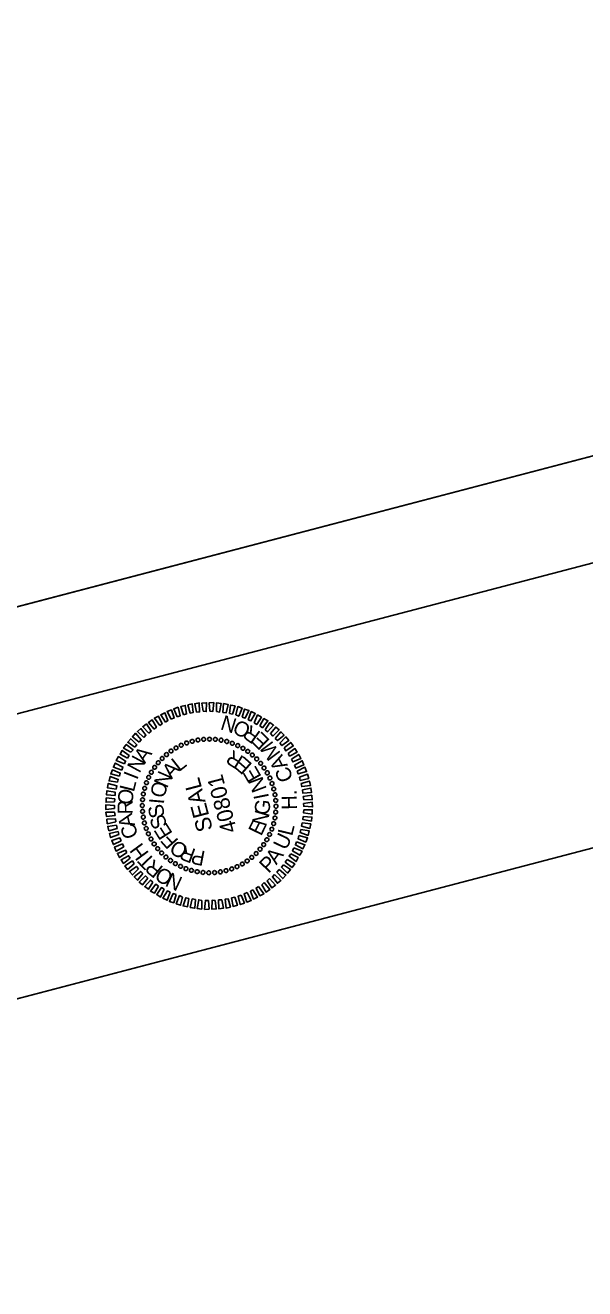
# Model space of a CAD drawing. Extents: x 1366711 to 1368206, y 878140 to 880064.
# Drawn here: x 1366973.2 to 1367176, y 879605.6 to 880063.8 of the extents above; entities that cross this region are included whole.
import ezdxf

# ---------------------------------------------------------------- set-up
doc = ezdxf.new("R2010")
doc.units = 0
for name, color, linetype in [('Exist Hydro Jurisdictional Stream or Body of Water Mitigable Cogo Number', 7, 'Continuous'), ('Exist Hydro Jurisdictional Stream or Body of Water NonMitigable', 7, 'Continuous'), ('Sheet_Data_Field_CELL', 7, 'Continuous'), ('Sheet_Data_Text_CELL', 7, 'Continuous'), ('Sheet_Plan_CELL', 7, 'Continuous')]:
    doc.layers.add(name, color=color, linetype=linetype)

msp = doc.modelspace()

# ---------------------------------------------------------------- linework, layer by layer
at = {"layer": 'Exist Hydro Jurisdictional Stream or Body of Water Mitigable Cogo Number'}
for p, q in [((1367748.14, 880017.97), (1366756.62, 879758.15)), ((1367773.49, 879921.24), (1366781.97, 879661.42))]:
    msp.add_line(p, q, dxfattribs=at)
at = {"layer": 'Exist Hydro Jurisdictional Stream or Body of Water NonMitigable'}
msp.add_line((1367774.9, 880063.78), (1366710.84, 879784.92), dxfattribs=at)
at = {"layer": 'Sheet_Data_Field_CELL'}
for p, q in [((1367037.9, 879804.8), (1367037.9, 879804.8)), ((1367039.98, 879804.93), (1367039.98, 879804.93)), ((1367042.11, 879804.82), (1367042.11, 879804.82)), ((1367026.03, 879800.61), (1367026.03, 879800.61)), ((1367027.83, 879801.72), (1367027.83, 879801.72)), ((1367029.77, 879802.66), (1367029.77, 879802.66)), ((1367031.69, 879803.5), (1367031.69, 879803.5)), ((1367033.73, 879804.12), (1367033.73, 879804.12)), ((1367035.81, 879804.56), (1367035.81, 879804.56)), ((1367044.21, 879804.51), (1367044.21, 879804.51)), ((1367046.28, 879804.09), (1367046.28, 879804.09)), ((1367048.29, 879803.39), (1367048.29, 879803.39)), ((1367050.27, 879802.6), (1367050.27, 879802.6)), ((1367052.1, 879801.61), (1367052.1, 879801.61)), ((1367053.93, 879800.46), (1367053.93, 879800.46)), ((1367021.36, 879796.34), (1367021.36, 879796.34)), ((1367022.83, 879797.9), (1367022.83, 879797.9)), ((1367024.38, 879799.34), (1367024.38, 879799.34)), ((1367055.55, 879799.16), (1367055.55, 879799.16)), ((1367057.11, 879797.69), (1367057.11, 879797.69)), ((1367058.55, 879796.14), (1367058.55, 879796.14)), ((1367017.92, 879791.06), (1367017.92, 879791.06)), ((1367018.91, 879792.89), (1367018.91, 879792.89)), ((1367020.06, 879794.71), (1367020.06, 879794.71)), ((1367059.82, 879794.49), (1367059.82, 879794.49)), ((1367060.93, 879792.69), (1367060.93, 879792.69)), ((1367016.43, 879787.07), (1367016.43, 879787.07)), ((1367017.13, 879789.08), (1367017.13, 879789.08)), ((1367061.87, 879790.75), (1367061.87, 879790.75)), ((1367062.71, 879788.83), (1367062.71, 879788.83)), ((1367063.33, 879786.8), (1367063.33, 879786.8)), ((1367015.7, 879782.9), (1367015.7, 879782.9)), ((1367016.01, 879785), (1367016.01, 879785)), ((1367063.77, 879784.71), (1367063.77, 879784.71)), ((1367064.01, 879782.62), (1367064.01, 879782.62)), ((1367015.59, 879780.77), (1367015.59, 879780.77)), ((1367015.72, 879778.69), (1367015.72, 879778.69)), ((1367039.86, 879780.66), (1367039.86, 879780.66)), ((1367064.03, 879778.41), (1367064.03, 879778.41)), ((1367064.14, 879780.55), (1367064.14, 879780.55)), ((1367015.96, 879776.6), (1367015.96, 879776.6)), ((1367016.4, 879774.52), (1367016.4, 879774.52)), ((1367063.3, 879774.24), (1367063.3, 879774.24)), ((1367063.72, 879776.31), (1367063.72, 879776.31)), ((1367017.02, 879772.48), (1367017.02, 879772.48)), ((1367017.86, 879770.56), (1367017.86, 879770.56)), ((1367018.8, 879768.62), (1367018.8, 879768.62)), ((1367060.82, 879768.42), (1367060.82, 879768.42)), ((1367061.81, 879770.26), (1367061.81, 879770.26)), ((1367062.6, 879772.24), (1367062.6, 879772.24)), ((1367019.91, 879766.82), (1367019.91, 879766.82)), ((1367021.18, 879765.17), (1367021.18, 879765.17)), ((1367022.62, 879763.62), (1367022.62, 879763.62)), ((1367058.37, 879764.98), (1367058.37, 879764.98)), ((1367059.67, 879766.59), (1367059.67, 879766.59)), ((1367024.18, 879762.15), (1367024.18, 879762.15)), ((1367025.8, 879760.85), (1367025.8, 879760.85)), ((1367027.63, 879759.7), (1367027.63, 879759.7)), ((1367051.9, 879759.6), (1367051.9, 879759.6)), ((1367053.7, 879760.7), (1367053.7, 879760.7)), ((1367055.35, 879761.97), (1367055.35, 879761.97)), ((1367056.9, 879763.41), (1367056.9, 879763.41)), ((1367029.46, 879758.71), (1367029.46, 879758.71)), ((1367031.45, 879757.92), (1367031.45, 879757.92)), ((1367033.45, 879757.22), (1367033.45, 879757.22)), ((1367035.52, 879756.8), (1367035.52, 879756.8)), ((1367037.62, 879756.49), (1367037.62, 879756.49)), ((1367039.76, 879756.38), (1367039.76, 879756.38)), ((1367041.83, 879756.51), (1367041.83, 879756.51)), ((1367043.92, 879756.75), (1367043.92, 879756.75)), ((1367046.01, 879757.19), (1367046.01, 879757.19)), ((1367048.04, 879757.81), (1367048.04, 879757.81)), ((1367049.96, 879758.65), (1367049.96, 879758.65))]:
    msp.add_line(p, q, dxfattribs=at)
for points in [[(1367024.01, 879811.03), (1367022.3, 879813.71), (1367023.81, 879814.44), (1367024.91, 879811.59)], [(1367026.13, 879812.08), (1367024.62, 879814.92), (1367026.16, 879815.5), (1367027.19, 879812.58)], [(1367028.28, 879812.98), (1367027.06, 879815.9), (1367028.61, 879816.44), (1367029.37, 879813.39)], [(1367030.59, 879813.68), (1367029.6, 879816.67), (1367031.18, 879817.11), (1367031.71, 879814)], [(1367032.93, 879814.29), (1367032.17, 879817.34), (1367033.74, 879817.68), (1367034.07, 879814.51)], [(1367035.23, 879814.68), (1367034.67, 879817.74), (1367036.3, 879818), (1367036.41, 879814.77)], [(1367037.71, 879814.98), (1367037.27, 879817.97), (1367038.94, 879818.09), (1367038.79, 879814.88)], [(1367040.11, 879815), (1367039.9, 879818.05), (1367041.53, 879818.16), (1367041.19, 879814.9)], [(1367042.54, 879814.93), (1367042.56, 879818.05), (1367044.18, 879817.85), (1367043.66, 879814.69)], [(1367044.85, 879814.57), (1367045.11, 879817.76), (1367046.74, 879817.47), (1367046, 879814.4)], [(1367047.24, 879814.24), (1367047.67, 879817.22), (1367049.3, 879816.93), (1367048.29, 879813.94)], [(1367049.56, 879813.69), (1367050.22, 879816.69), (1367051.79, 879816.12), (1367050.61, 879813.18)], [(1367051.81, 879812.82), (1367052.69, 879815.77), (1367054.29, 879815.27), (1367052.87, 879812.46)], [(1367053.97, 879811.92), (1367055.11, 879814.85), (1367056.6, 879814.16), (1367054.99, 879811.5)], [(1367017.96, 879807.02), (1367015.79, 879809.38), (1367017.11, 879810.4), (1367018.85, 879807.78)], [(1367019.91, 879808.48), (1367017.9, 879810.97), (1367019.2, 879811.89), (1367020.75, 879809.21)], [(1367021.93, 879809.85), (1367020.02, 879812.52), (1367021.48, 879813.23), (1367022.82, 879810.45)], [(1367056.2, 879810.79), (1367057.44, 879813.69), (1367058.83, 879812.83), (1367057.15, 879810.25)], [(1367058.26, 879809.71), (1367059.73, 879812.33), (1367061.16, 879811.53), (1367059.16, 879809.01)], [(1367060.22, 879808.25), (1367061.89, 879810.88), (1367063.22, 879809.9), (1367061.07, 879807.54)], [(1367012.94, 879802), (1367010.35, 879803.73), (1367011.45, 879805), (1367013.67, 879802.81)], [(1367014.51, 879803.75), (1367012.05, 879805.72), (1367013.2, 879806.99), (1367015.26, 879804.66)], [(1367016.22, 879805.53), (1367013.86, 879807.68), (1367015.13, 879808.69), (1367016.94, 879806.34)], [(1367062.11, 879806.88), (1367064, 879809.26), (1367065.22, 879808.3), (1367062.96, 879806.01)], [(1367063.85, 879805.16), (1367065.88, 879807.58), (1367067.03, 879806.35), (1367064.66, 879804.43)], [(1367065.53, 879803.47), (1367067.72, 879805.69), (1367068.77, 879804.43), (1367066.23, 879802.56)], [(1367010.3, 879798), (1367007.55, 879799.38), (1367008.36, 879800.81), (1367010.85, 879798.91)], [(1367011.52, 879800.1), (1367008.83, 879801.65), (1367009.81, 879802.98), (1367012.27, 879801.01)], [(1367067.08, 879801.7), (1367069.44, 879803.67), (1367070.39, 879802.43), (1367067.69, 879800.61)], [(1367068.46, 879799.63), (1367070.95, 879801.48), (1367071.78, 879800.16), (1367069.06, 879798.74)], [(1367008.2, 879793.69), (1367005.16, 879794.7), (1367005.84, 879796.19), (1367008.6, 879794.76)], [(1367009.14, 879795.87), (1367006.19, 879797.1), (1367006.99, 879798.53), (1367009.6, 879796.95)], [(1367069.7, 879797.57), (1367072.35, 879799.36), (1367073.12, 879797.87), (1367070.2, 879796.65)], [(1367070.83, 879795.48), (1367073.6, 879797.06), (1367074.17, 879795.56), (1367071.29, 879794.4)], [(1367006.59, 879789.23), (1367003.59, 879789.74), (1367003.99, 879791.36), (1367006.9, 879790.27)], [(1367007.34, 879791.4), (1367004.18, 879792.26), (1367004.82, 879793.75), (1367007.61, 879792.58)], [(1367071.74, 879793.32), (1367074.57, 879794.67), (1367075.2, 879793.14), (1367072.19, 879792.25)], [(1367072.63, 879791.06), (1367075.58, 879792.14), (1367075.97, 879790.59), (1367072.89, 879789.93)], [(1367006.12, 879786.79), (1367003.05, 879787.18), (1367003.3, 879788.81), (1367006.35, 879787.96)], [(1367073.21, 879788.81), (1367076.23, 879789.66), (1367076.62, 879788.12), (1367073.47, 879787.69)], [(1367073.72, 879786.45), (1367076.79, 879787.11), (1367076.95, 879785.5), (1367073.85, 879785.28)], [(1367005.58, 879782.12), (1367002.5, 879782.01), (1367002.56, 879783.58), (1367005.63, 879783.19)], [(1367005.83, 879784.45), (1367002.6, 879784.69), (1367002.79, 879786.16), (1367005.85, 879785.61)], [(1367073.97, 879784.11), (1367077.07, 879784.53), (1367077.27, 879782.93), (1367074.15, 879782.95)], [(1367074.13, 879781.59), (1367077.28, 879781.98), (1367077.36, 879780.29), (1367074.17, 879780.55)], [(1367005.6, 879779.72), (1367002.45, 879779.33), (1367002.38, 879781.02), (1367005.56, 879780.76)], [(1367005.75, 879777.2), (1367002.66, 879776.78), (1367002.46, 879778.38), (1367005.58, 879778.36)], [(1367074.15, 879779.19), (1367077.23, 879779.3), (1367077.17, 879777.73), (1367074.1, 879778.12)], [(1367006.01, 879774.86), (1367002.93, 879774.2), (1367002.78, 879775.81), (1367005.88, 879776.03)], [(1367006.52, 879772.5), (1367003.5, 879771.65), (1367003.12, 879773.2), (1367006.26, 879773.63)], [(1367073.61, 879774.52), (1367076.68, 879774.13), (1367076.43, 879772.51), (1367073.38, 879773.36)], [(1367073.9, 879776.86), (1367077.13, 879776.62), (1367076.94, 879775.16), (1367073.88, 879775.7)], [(1367007.1, 879770.25), (1367004.15, 879769.17), (1367003.76, 879770.72), (1367006.84, 879771.38)], [(1367007.99, 879767.99), (1367005.16, 879766.64), (1367004.53, 879768.17), (1367007.54, 879769.07)], [(1367072.39, 879769.92), (1367075.55, 879769.04), (1367074.91, 879767.56), (1367072.12, 879768.74)], [(1367073.14, 879772.08), (1367076.14, 879771.57), (1367075.74, 879769.95), (1367072.83, 879771.04)], [(1367008.9, 879765.84), (1367006.13, 879764.26), (1367005.56, 879765.75), (1367008.44, 879766.91)], [(1367010.04, 879763.75), (1367007.38, 879761.95), (1367006.61, 879763.44), (1367009.53, 879764.66)], [(1367070.59, 879765.44), (1367073.54, 879764.22), (1367072.74, 879762.79), (1367070.14, 879764.36)], [(1367071.53, 879767.62), (1367074.57, 879766.61), (1367073.89, 879765.12), (1367071.13, 879766.55)], [(1367011.27, 879761.68), (1367008.78, 879759.83), (1367007.95, 879761.15), (1367010.67, 879762.57)], [(1367012.65, 879759.61), (1367010.29, 879757.65), (1367009.34, 879758.89), (1367012.05, 879760.7)], [(1367066.79, 879759.31), (1367069.38, 879757.58), (1367068.28, 879756.31), (1367066.06, 879758.5)], [(1367068.21, 879761.21), (1367070.9, 879759.66), (1367069.92, 879758.33), (1367067.46, 879760.3)], [(1367069.43, 879763.31), (1367072.18, 879761.93), (1367071.37, 879760.49), (1367068.88, 879762.4)], [(1367014.2, 879757.84), (1367012.02, 879755.62), (1367010.96, 879756.88), (1367013.5, 879758.75)], [(1367015.88, 879756.16), (1367013.85, 879753.73), (1367012.71, 879754.96), (1367015.07, 879756.88)], [(1367017.62, 879754.43), (1367015.73, 879752.05), (1367014.51, 879753.01), (1367016.77, 879755.3)], [(1367063.51, 879755.78), (1367065.87, 879753.63), (1367064.6, 879752.62), (1367062.79, 879754.97)], [(1367065.22, 879757.56), (1367067.68, 879755.59), (1367066.53, 879754.32), (1367064.47, 879756.65)], [(1367019.51, 879753.06), (1367017.84, 879750.43), (1367016.51, 879751.41), (1367018.66, 879753.77)], [(1367021.47, 879751.6), (1367020, 879748.98), (1367018.57, 879749.78), (1367020.58, 879752.3)], [(1367023.53, 879750.53), (1367022.29, 879747.62), (1367020.9, 879748.48), (1367022.58, 879751.06)], [(1367025.76, 879749.39), (1367024.62, 879746.46), (1367023.13, 879747.15), (1367024.74, 879749.81)], [(1367055.72, 879750.28), (1367057.43, 879747.6), (1367055.93, 879746.87), (1367054.82, 879749.73)], [(1367057.8, 879751.46), (1367059.7, 879748.79), (1367058.25, 879748.08), (1367056.91, 879750.86)], [(1367059.82, 879752.83), (1367061.83, 879750.34), (1367060.53, 879749.42), (1367058.98, 879752.1)], [(1367061.77, 879754.29), (1367063.94, 879751.93), (1367062.62, 879750.91), (1367060.88, 879753.53)], [(1367027.92, 879748.49), (1367027.04, 879745.54), (1367025.45, 879746.04), (1367026.87, 879748.85)], [(1367030.17, 879747.62), (1367029.51, 879744.62), (1367027.94, 879745.19), (1367029.12, 879748.13)], [(1367032.48, 879747.07), (1367032.07, 879744.09), (1367030.43, 879744.38), (1367031.44, 879747.38)], [(1367034.89, 879746.74), (1367034.63, 879743.55), (1367032.99, 879743.84), (1367033.73, 879746.91)], [(1367037.19, 879746.38), (1367037.17, 879743.26), (1367035.55, 879743.46), (1367036.07, 879746.62)], [(1367039.62, 879746.31), (1367039.83, 879743.26), (1367038.2, 879743.15), (1367038.54, 879746.41)], [(1367042.03, 879746.33), (1367042.46, 879743.34), (1367040.79, 879743.23), (1367040.94, 879746.43)], [(1367044.5, 879746.63), (1367045.06, 879743.57), (1367043.42, 879743.31), (1367043.32, 879746.55)], [(1367046.8, 879747.02), (1367047.56, 879743.97), (1367046, 879743.63), (1367045.66, 879746.8)], [(1367049.14, 879747.63), (1367050.13, 879744.64), (1367048.54, 879744.2), (1367048.02, 879747.31)], [(1367051.45, 879748.33), (1367052.68, 879745.41), (1367051.12, 879744.87), (1367050.36, 879747.92)], [(1367053.61, 879749.23), (1367055.11, 879746.39), (1367053.57, 879745.81), (1367052.54, 879748.73)]]:
    msp.add_lwpolyline(points, close=True, dxfattribs=at)
for centre, major_axis in [((1367033.72, 879804.1), (-0.176, 0.673)), ((1367035.79, 879804.54), (-0.117, 0.686)), ((1367037.89, 879804.81), (-0.057, 0.693)), ((1367040, 879804.89), (0.004, 0.696)), ((1367042.11, 879804.78), (0.064, 0.693)), ((1367044.2, 879804.5), (0.125, 0.685)), ((1367046.27, 879804.03), (0.184, 0.671)), ((1367026.07, 879800.58), (-0.396, 0.572)), ((1367027.86, 879801.71), (-0.345, 0.604)), ((1367029.74, 879802.67), (-0.291, 0.632)), ((1367031.7, 879803.47), (-0.234, 0.655)), ((1367048.28, 879803.38), (0.242, 0.652)), ((1367050.23, 879802.56), (0.298, 0.629)), ((1367052.1, 879801.57), (0.351, 0.601)), ((1367053.88, 879800.43), (0.402, 0.568)), ((1367021.39, 879796.33), (-0.531, 0.45)), ((1367022.82, 879797.88), (-0.489, 0.495)), ((1367024.39, 879799.3), (-0.444, 0.535)), ((1367055.55, 879799.13), (0.45, 0.531)), ((1367057.1, 879797.7), (0.495, 0.489)), ((1367058.52, 879796.13), (0.535, 0.444)), ((1367017.96, 879791.02), (-0.629, 0.298)), ((1367018.94, 879792.89), (-0.601, 0.351)), ((1367020.09, 879794.66), (-0.568, 0.402)), ((1367059.79, 879794.44), (0.572, 0.396)), ((1367060.92, 879792.66), (0.604, 0.345)), ((1367061.89, 879790.77), (0.632, 0.291)), ((1367016.49, 879787.05), (-0.671, 0.184)), ((1367017.14, 879789.07), (-0.652, 0.242)), ((1367062.68, 879788.82), (0.655, 0.234)), ((1367063.31, 879786.8), (0.673, 0.176)), ((1367015.73, 879782.9), (-0.693, 0.064)), ((1367016.02, 879784.99), (-0.685, 0.125)), ((1367063.76, 879784.73), (0.686, 0.117)), ((1367064.02, 879782.63), (0.693, 0.057)), ((1367015.63, 879780.79), (-0.696, 0.004)), ((1367015.71, 879778.67), (-0.693, -0.057)), ((1367015.97, 879776.58), (-0.686, -0.117)), ((1367064, 879778.41), (0.693, -0.064)), ((1367064.1, 879780.52), (0.696, -0.004)), ((1367016.42, 879774.51), (-0.673, -0.176)), ((1367017.05, 879772.49), (-0.655, -0.234)), ((1367062.59, 879772.24), (0.652, -0.242)), ((1367063.24, 879774.25), (0.671, -0.184)), ((1367063.71, 879776.31), (0.685, -0.125)), ((1367017.84, 879770.53), (-0.632, -0.291)), ((1367018.81, 879768.65), (-0.604, -0.345)), ((1367060.79, 879768.42), (0.601, -0.351)), ((1367061.77, 879770.29), (0.629, -0.298)), ((1367019.94, 879766.86), (-0.572, -0.396)), ((1367021.21, 879765.18), (-0.535, -0.444)), ((1367022.63, 879763.61), (-0.495, -0.489)), ((1367056.91, 879763.42), (0.489, -0.495)), ((1367058.35, 879764.97), (0.531, -0.45)), ((1367059.64, 879766.64), (0.568, -0.402)), ((1367024.18, 879762.17), (-0.45, -0.531)), ((1367025.86, 879760.88), (-0.402, -0.568)), ((1367027.63, 879759.73), (-0.351, -0.601)), ((1367029.5, 879758.74), (-0.298, -0.629)), ((1367049.99, 879758.63), (0.291, -0.632)), ((1367051.87, 879759.6), (0.345, -0.604)), ((1367053.66, 879760.72), (0.396, -0.572)), ((1367055.34, 879762), (0.444, -0.535)), ((1367031.45, 879757.92), (-0.242, -0.652)), ((1367033.46, 879757.28), (-0.184, -0.671)), ((1367035.53, 879756.81), (-0.125, -0.685)), ((1367037.62, 879756.52), (-0.064, -0.693)), ((1367039.73, 879756.42), (-0.004, -0.696)), ((1367041.84, 879756.5), (0.057, -0.693)), ((1367043.94, 879756.76), (0.117, -0.686)), ((1367046.01, 879757.21), (0.176, -0.673)), ((1367048.03, 879757.83), (0.234, -0.655))]:
    msp.add_ellipse(centre, major_axis=major_axis, ratio=0.999708, dxfattribs=at)
at = {"layer": 'Sheet_Data_Text_CELL'}
msp.add_lwpolyline([(1367141.8, 878140.46), (1366710.84, 879784.92), (1367774.9, 880063.78), (1368205.86, 878419.32)], close=True, dxfattribs=at)
at = {"layer": 'Sheet_Plan_CELL'}
msp.add_lwpolyline([(1367168.57, 878186.24), (1366781.97, 879661.42), (1367773.49, 879921.26), (1368160.08, 878446.08)], close=True, dxfattribs=at)

# ---------------------------------------------------------------- texts
at = {"layer": 'Sheet_Data_Field_CELL'}
for s, height, rotation, p in [('N', 5.46, 162.2488, (1367050.31, 879812.11)), ('O', 5.46, 153.3152, (1367055.45, 879809.7)), ('R', 5.46, 144.3093, (1367058.9, 879807.25)), ('E', 5.46, 135.9223, (1367062.18, 879804.43)), ('A', 5.45, 54.3023, (1367016.59, 879795.79)), ('R', 5.45, 148.1665, (1367052.7, 879798.4)), ('M', 5.46, 126.9479, (1367066.01, 879799.75)), ('N', 5.45, 61.504, (1367014.62, 879792.28)), ('A', 5.45, 47.4454, (1367026.25, 879790.17)), ('L', 5.45, 38.086, (1367028.95, 879792.89)), ('E', 5.45, 138.8092, (1367055.81, 879795.72)), ('A', 5.46, 118.0142, (1367068.52, 879795.33)), ('I', 5.45, 68.7053, (1367013.74, 879789.87)), ('N', 5.45, 66.1617, (1367024.58, 879786.84)), ('SEAL', 5.796, 104.8532, (1367041.25, 879772.16)), ('SEAL', 5.796, 104.6851, (1367041.25, 879772.15)), ('40801', 5.798, 104.6851, (1367050.04, 879771.65)), ('E', 5.45, 120.0969, (1367059.01, 879791.29)), ('N', 5.45, 110.7415, (1367060.86, 879786.84)), ('C', 5.46, 109.0084, (1367070.42, 879790.38)), ('O', 5.45, 83.1063, (1367011.99, 879780.9)), ('L', 5.45, 75.906, (1367012.57, 879785.48)), ('O', 5.45, 75.5186, (1367023.59, 879783.21)), ('R', 5.45, 90.3062, (1367012.17, 879777.59)), ('I', 5.45, 84.8747, (1367023.46, 879781.16)), ('I', 5.45, 101.3863, (1367061.6, 879783.69)), ('G', 5.45, 82.6754, (1367061.54, 879777.1)), ('H.', 5.46, 90.9953, (1367071.69, 879779.3)), ('A', 5.45, 104.7054, (1367013.08, 879773.63)), ('S', 5.45, 103.5855, (1367023.94, 879776.98)), ('S', 5.45, 112.9407, (1367024.92, 879773.64)), ('N', 5.45, 73.3191, (1367060.44, 879772.98)), ('C', 5.45, 111.905, (1367014.39, 879770.03)), ('E', 5.45, 122.2962, (1367026.8, 879770.7)), ('E', 5.45, 63.962, (1367058.71, 879769.48)), ('L', 5.46, 76.2009, (1367069.94, 879769.52)), ('F', 5.45, 131.6521, (1367029.03, 879768.12)), ('U', 5.46, 64.4578, (1367067.76, 879764.31)), ('H', 5.45, 126.3046, (1367018.24, 879763.48)), ('O', 5.45, 150.3664, (1367032.64, 879765.82)), ('R', 5.45, 159.7248, (1367035.38, 879764.83)), ('P', 5.45, 169.084, (1367038.77, 879764.18)), ('A', 5.46, 53.7081, (1367064.26, 879759.06)), ('T', 5.45, 133.5049, (1367020.62, 879760.89)), ('R', 5.45, 140.7056, (1367023.56, 879758.3)), ('P', 5.46, 46.3622, (1367061.43, 879755.97)), ('O', 5.45, 147.9069, (1367027.34, 879755.9)), ('N', 5.45, 155.1086, (1367030.64, 879754.52))]:
    msp.add_text(s, height=height, rotation=rotation, dxfattribs=at).set_placement(p)

doc.saveas('drawing.dxf')
